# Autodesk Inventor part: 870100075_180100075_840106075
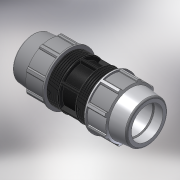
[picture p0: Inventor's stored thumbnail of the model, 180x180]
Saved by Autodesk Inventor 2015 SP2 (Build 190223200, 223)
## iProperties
Created: 2017-02
Part Number: 870100075_180100075_840106075
Material: Generic
Description: PLASSON COUPLER 75-75
Document SubType Name: Modeling
Designer: KIM
Mass: 3885.53 g
Surface Area: 4713.66 cm^2
Volume: 3885.53 cm^3
Density: 1 g/cm^3
Appearance: Default
Author: KIM
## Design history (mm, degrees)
derived "87010.ipt"
feature "Solid1::87010.ipt"
tag "TaggingFeature1"
body "Solid1"
other parameters: "d1" = 289, "d2" = 75, "d4" = 24.08333, "d5" = 41.28571, "d7" = 132, "d8" = 99, "d9" = 41.28571, "d11" = 4.12857, "d12" = 105.6, "d13" = 120 deg, "d14" = 105, "d15" = 6 deg, "d16" = 118.8, "d18" = 3.75, "d19" = 35 deg, "d20" = 17.5 deg, "d21" = 122.76, "d23" = 0, "d25" = 360 deg, "d27" = 2.64, "d33" = 1.5, "d34" = 6.6, "d36" = 0, "d37" = 1.5, "d38" = 1.5, "d40" = 360 deg, "d42" = 52.02, "d46" = 2.25, "d50" = 3.6125, "d51" = 0, "d53" = 2.64229, "d54" = 2.64229, "d57" = 5.28457, "d62" = 116.424, "d64" = 67.5, "d65" = 143, "d_" = 75, "E_" = 132, "H_" = 289, "l_" = 143, "d52" = 26.42286
